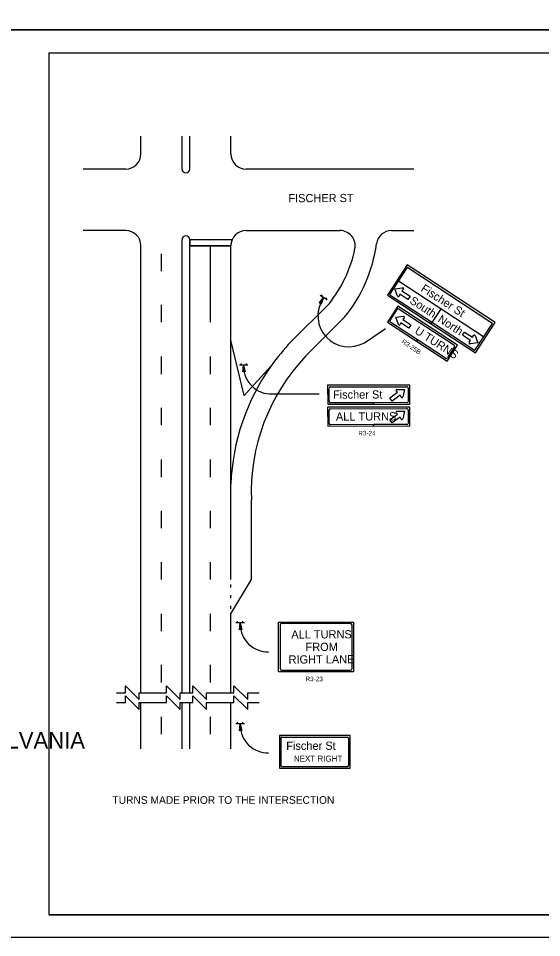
# Model space of a CAD drawing. Extents: x 644898 to 648326, y 298294 to 300670.
# Drawn here: x 646600 to 646943, y 298888 to 299490 of the extents above; entities that cross this region are included whole.
import ezdxf

# ---------------------------------------------------------------- set-up
doc = ezdxf.new("R2010")
doc.units = 0
for name, color, linetype in [('1', 7, 'Continuous'), ('2', 7, 'Continuous'), ('XCS-GRID-MIN', 7, 'Continuous')]:
    doc.layers.add(name, color=color, linetype=linetype)

msp = doc.modelspace()

# ---------------------------------------------------------------- linework, layer by layer
at = {"layer": '1'}
for p, q in [((646620.32, 299467.49), (647406.32, 299467.49)), ((646620.32, 299467.49), (646620.32, 298903.49)), ((647406.32, 298903.49), (646620.32, 298903.49)), ((646620.32, 298903.49), (647206.32, 298903.49))]:
    msp.add_line(p, q, dxfattribs=at)
at = {"layer": '2'}
for p, q in [((646680.58, 299401.42), (646680.58, 299412.84)), ((646707.46, 299391.42), (646707.46, 299412.84)), ((646712.55, 299391.42), (646712.55, 299412.84)), ((646739.42, 299401.42), (646739.42, 299412.84)), ((646670.58, 299391.42), (646642.84, 299391.42)), ((646859.13, 299391.42), (646749.42, 299391.42)), ((646670.58, 299351.17), (646642.84, 299351.17)), ((646749.42, 299351.17), (646810.8, 299351.17)), ((646844.69, 299351.17), (646859.13, 299351.17)), ((646707.46, 299167.76), (646707.46, 299345.17)), ((646712.55, 299167.76), (646712.55, 299345.17)), ((646740.26, 299345.17), (646712.55, 299345.17)), ((646680.58, 299167.76), (646680.58, 299341.17)), ((646739.42, 299341.17), (646712.55, 299341.17)), ((646726.05, 299291.14), (646726.05, 299341.17)), ((646739.42, 299279.33), (646739.42, 299341.17)), ((646694.08, 299324.64), (646694.08, 299336.01)), ((646854.81, 299328.7), (646841.95, 299308.85)), ((646843.42, 299309.37), (646854.83, 299326.84)), ((646912.36, 299291.05), (646854.81, 299328.7)), ((646855.27, 299326.95), (646910.33, 299290.84)), ((646846.71, 299313.09), (646851.77, 299313.7)), ((646848.51, 299308.22), (646846.71, 299313.09)), ((646849.2, 299318.29), (646904.82, 299281.86)), ((646852.36, 299312.69), (646851.41, 299311.67)), ((646802.47, 299305.72), (646797.87, 299308.72)), ((646798.7, 299308.17), (646799.32, 299309.12)), ((646801.63, 299306.26), (646802.25, 299307.21)), ((646841.95, 299308.85), (646869.52, 299290.81)), ((646870.05, 299291.62), (646843.53, 299308.94)), ((646850.1, 299309.45), (646849.58, 299308.24)), ((646855.34, 299306.02), (646850.1, 299309.45)), ((646851.41, 299311.67), (646856.74, 299308.14)), ((646856.74, 299308.14), (646855.34, 299306.02)), ((646694.08, 299291.14), (646694.08, 299302.51)), ((646778.77, 299278.34), (646803.69, 299303.26)), ((646848.72, 299301.64), (646841.98, 299291.24)), ((646887.77, 299276.09), (646848.72, 299301.64)), ((646843.78, 299292.32), (646848.34, 299299.41)), ((646847.33, 299294.46), (646852.39, 299295.07)), ((646849.14, 299289.58), (646847.33, 299294.46)), ((646849.72, 299299.76), (646885.27, 299276.57)), ((646877.01, 299300.07), (646870.63, 299290.32)), ((646788.51, 299269.08), (646813.67, 299294.24)), ((646841.98, 299291.24), (646861.05, 299278.82)), ((646861.52, 299279.59), (646844.07, 299291.03)), ((646850.72, 299290.82), (646850.2, 299289.61)), ((646855.96, 299287.39), (646850.72, 299290.82)), ((646852.98, 299294.06), (646852.03, 299293.04)), ((646852.03, 299293.04), (646857.36, 299289.51)), ((646857.36, 299289.51), (646855.96, 299287.39)), ((646870.05, 299291.62), (646869.52, 299290.81)), ((646869.52, 299290.81), (646870.05, 299291.62)), ((646869.52, 299290.81), (646899.49, 299271.2)), ((646898.69, 299272.92), (646870.05, 299291.62)), ((646910.45, 299290.41), (646899.12, 299273.04)), ((646899.49, 299271.2), (646912.36, 299291.05)), ((646826.85, 299277.78), (646840.71, 299287.04)), ((646891.09, 299282.63), (646892.49, 299284.76)), ((646896.42, 299279.11), (646891.09, 299282.63)), ((646892.49, 299284.76), (646897.73, 299281.32)), ((646897.73, 299281.32), (646898.25, 299282.53)), ((646899.31, 299282.56), (646901.12, 299277.69)), ((646739.42, 299167.76), (646739.42, 299279.33)), ((646861.05, 299278.82), (646861.52, 299279.59)), ((646861.52, 299279.59), (646861.05, 299278.82)), ((646861.05, 299278.82), (646880.99, 299265.72)), ((646879.86, 299267.67), (646861.52, 299279.59)), ((646895.47, 299278.08), (646896.42, 299279.11)), ((646901.12, 299277.69), (646896.06, 299277.07)), ((646880.99, 299265.72), (646887.77, 299276.09)), ((646885.76, 299275.02), (646881.17, 299268.01)), ((646694.08, 299257.26), (646694.08, 299268.64)), ((646726.05, 299257.26), (646726.05, 299268.64)), ((646750.57, 299263.11), (646745.07, 299263.11)), ((646746.07, 299263.11), (646746.07, 299264.23)), ((646749.57, 299263.11), (646749.57, 299264.23)), ((646856.7, 299249.96), (646802.8, 299249.96)), ((646802.8, 299249.96), (646802.85, 299237.57)), ((646803.76, 299239.45), (646803.73, 299247.91)), ((646804.67, 299248.92), (646854.34, 299249)), ((646848.59, 299245.34), (646847.64, 299246.25)), ((646847.98, 299247.26), (646853.18, 299247.25)), ((646853.18, 299247.25), (646851.99, 299242.3)), ((646855.6, 299247.97), (646855.6, 299239.59)), ((646856.7, 299237.57), (646856.7, 299249.96)), ((646766.45, 299244.23), (646797.31, 299244.23)), ((646843.55, 299241.63), (646848.59, 299245.34)), ((646845.05, 299239.57), (646843.55, 299241.63)), ((646850.21, 299243.34), (646845.05, 299239.57)), ((646850.84, 299242.1), (646850.21, 299243.34)), ((646694.08, 299223.76), (646694.08, 299235.14)), ((646726.05, 299223.76), (646726.05, 299235.14)), ((646856.7, 299235.62), (646802.8, 299235.62)), ((646802.8, 299235.62), (646802.85, 299223.23)), ((646802.85, 299237.57), (646832.84, 299237.62)), ((646804.67, 299234.59), (646854.34, 299234.66)), ((646832.81, 299238.51), (646804.75, 299238.42)), ((646854.69, 299238.58), (646832.81, 299238.51)), ((646832.84, 299237.62), (646832.81, 299238.51)), ((646832.81, 299238.51), (646832.84, 299237.62)), ((646832.84, 299237.62), (646856.7, 299237.57)), ((646856.7, 299223.23), (646856.7, 299235.62)), ((646803.76, 299225.12), (646803.73, 299233.58)), ((646843.55, 299227.29), (646848.59, 299231.01)), ((646850.21, 299229.01), (646845.05, 299225.24)), ((646848.59, 299231.01), (646847.64, 299231.92)), ((646847.98, 299232.92), (646853.18, 299232.92)), ((646850.84, 299227.76), (646850.21, 299229.01)), ((646853.18, 299232.92), (646851.99, 299227.96)), ((646855.6, 299233.63), (646855.6, 299225.25)), ((646802.85, 299223.23), (646832.84, 299223.28)), ((646832.81, 299224.18), (646804.75, 299224.09)), ((646854.69, 299224.25), (646832.81, 299224.18)), ((646832.84, 299223.28), (646832.81, 299224.18)), ((646832.81, 299224.18), (646832.84, 299223.28)), ((646832.84, 299223.28), (646856.7, 299223.23)), ((646845.05, 299225.24), (646843.55, 299227.29)), ((646694.08, 299189.89), (646694.08, 299201.26)), ((646726.05, 299189.89), (646726.05, 299201.26)), ((646752.88, 299167.76), (646752.88, 299174.67)), ((646680.58, 299048.76), (646680.58, 299167.76)), ((646694.08, 299156.39), (646694.08, 299167.76)), ((646707.46, 299048.76), (646707.46, 299167.76)), ((646712.55, 299048.76), (646712.55, 299167.76)), ((646726.05, 299156.39), (646726.05, 299167.76)), ((646739.42, 299122.89), (646739.42, 299167.76)), ((646752.88, 299122.89), (646752.88, 299167.76)), ((646694.08, 299122.89), (646694.08, 299134.26)), ((646726.05, 299122.89), (646726.05, 299134.26)), ((646739.42, 299100.39), (646752.88, 299122.89)), ((646739.42, 299117.64), (646739.42, 299119.64)), ((646739.42, 299110.64), (646739.42, 299112.64)), ((646739.42, 299103.64), (646739.42, 299105.64)), ((646694.08, 299089.01), (646694.08, 299100.39)), ((646726.05, 299089.01), (646726.05, 299100.39)), ((646739.42, 299048.76), (646739.42, 299100.39)), ((646748.29, 299094.42), (646742.79, 299094.42)), ((646743.79, 299094.42), (646743.79, 299095.55)), ((646747.29, 299094.42), (646747.29, 299095.55)), ((646770.64, 299062.5), (646770.64, 299095)), ((646770.64, 299095), (646794.31, 299095)), ((646771.64, 299093), (646771.64, 299064.5)), ((646794.31, 299094), (646772.64, 299094)), ((646794.31, 299094), (646794.31, 299095)), ((646794.31, 299095), (646819.77, 299095)), ((646794.31, 299095), (646794.31, 299094)), ((646817.77, 299094), (646794.31, 299094)), ((646818.77, 299064.5), (646818.77, 299093)), ((646819.77, 299095), (646819.77, 299062.5)), ((646694.08, 299055.51), (646694.08, 299066.89)), ((646726.05, 299055.51), (646726.05, 299066.89)), ((646819.77, 299062.5), (646770.64, 299062.5)), ((646772.64, 299063.5), (646817.77, 299063.5)), ((646664.5, 299048.76), (646670.38, 299048.76)), ((646679.38, 299048.76), (646697.25, 299048.76)), ((646706.25, 299048.76), (646713.75, 299048.76)), ((646708.71, 299048.76), (646714.58, 299048.76)), ((646723.58, 299048.76), (646741.46, 299048.76)), ((646750.46, 299048.76), (646757.96, 299048.76)), ((646664.5, 299042.26), (646670.38, 299042.26)), ((646679.38, 299042.26), (646697.25, 299042.26)), ((646680.58, 299012.09), (646680.58, 299042.26)), ((646706.25, 299042.26), (646713.75, 299042.26)), ((646707.46, 299012.09), (646707.46, 299042.26)), ((646708.71, 299042.26), (646714.58, 299042.26)), ((646712.55, 299012.09), (646712.55, 299042.26)), ((646723.58, 299042.26), (646741.46, 299042.26)), ((646739.42, 299012.09), (646739.42, 299042.26)), ((646750.46, 299042.26), (646757.96, 299042.26)), ((646694.08, 299021.64), (646694.08, 299033.01)), ((646726.05, 299021.64), (646726.05, 299033.01)), ((646748.29, 299028.35), (646742.79, 299028.35)), ((646743.79, 299028.35), (646743.79, 299029.48)), ((646747.29, 299028.35), (646747.29, 299029.48)), ((646817.43, 299020.67), (646771.36, 299020.67)), ((646771.36, 299020.67), (646771.36, 299012.25)), ((646772.36, 299012.25), (646772.36, 299019.42)), ((646772.61, 299019.67), (646815.62, 299019.67)), ((646816.52, 299018.78), (646816.49, 299001.34)), ((646817.43, 298999.3), (646817.43, 299020.67)), ((646772.36, 299012.25), (646771.36, 299012.25)), ((646771.36, 299012.25), (646771.36, 298999.3)), ((646771.36, 299012.25), (646772.36, 299012.25)), ((646772.36, 299000.55), (646772.36, 299012.25)), ((646815.56, 299000.3), (646772.61, 299000.3)), ((646771.36, 298999.3), (646817.43, 298999.3))]:
    msp.add_line(p, q, dxfattribs=at)
for points in [[(646740.26, 299345.17), (646712.55, 299345.17), (646712.55, 299341.17), (646726.05, 299341.17), (646739.42, 299341.17)], [(646797.64, 299303.8), (646797.92, 299303.76), (646800.06, 299307.29), (646797.64, 299303.8), (646797.29, 299303.72), (646800.06, 299307.29), (646798.33, 299303.49), (646798.48, 299303.25), (646800.06, 299307.29), (646798.62, 299303.01), (646798.48, 299303.25)], [(646765.9, 299262.74), (646748.22, 299243.14), (646739.42, 299279.33)], [(646747.57, 299258.86), (646747.82, 299258.98), (646747.7, 299263.11), (646747.57, 299258.86), (646747.32, 299258.61), (646747.7, 299263.11), (646748.32, 299258.98), (646748.57, 299258.86), (646747.7, 299263.11), (646748.82, 299258.73), (646748.57, 299258.86)], [(646745.29, 299090.17), (646745.54, 299090.3), (646745.42, 299094.42), (646745.29, 299090.17), (646745.04, 299089.92), (646745.42, 299094.42), (646746.04, 299090.3), (646746.29, 299090.17), (646745.42, 299094.42), (646746.54, 299090.05), (646746.29, 299090.17)], [(646670.38, 299048.76), (646670.38, 299053.26), (646679.38, 299044.26), (646679.38, 299048.76)], [(646697.25, 299048.76), (646697.25, 299053.26), (646706.25, 299044.26), (646706.25, 299048.76)], [(646714.58, 299048.76), (646714.58, 299053.26), (646723.58, 299044.26), (646723.58, 299048.76)], [(646741.46, 299048.76), (646741.46, 299053.26), (646750.46, 299044.26), (646750.46, 299048.76)], [(646670.38, 299042.26), (646670.38, 299046.76), (646679.38, 299037.76), (646679.38, 299042.26)], [(646697.25, 299042.26), (646697.25, 299046.76), (646706.25, 299037.76), (646706.25, 299042.26)], [(646714.58, 299042.26), (646714.58, 299046.76), (646723.58, 299037.76), (646723.58, 299042.26)], [(646741.46, 299042.26), (646741.46, 299046.76), (646750.46, 299037.76), (646750.46, 299042.26)], [(646745.29, 299024.1), (646745.54, 299024.23), (646745.42, 299028.35), (646745.29, 299024.1), (646745.04, 299023.85), (646745.42, 299028.35), (646746.04, 299024.23), (646746.29, 299024.1), (646745.42, 299028.35), (646746.54, 299023.98), (646746.29, 299024.1)]]:
    msp.add_lwpolyline(points, dxfattribs=at)
for centre, radius, start, end in [((646670.58, 299401.42), 10, 270, 0), ((646749.42, 299401.42), 10, 180, 270), ((646710, 299391.42), 2.55, 180, 360), ((646670.58, 299341.17), 10, 0, 90), ((646749.42, 299341.17), 10, 90, 180), ((646810.8, 299341.17), 10, 348.55632, 89.99983), ((646844.69, 299341.17), 10, 90.00056, 172.16517), ((646710, 299345.17), 2.55, 0, 180), ((646749.42, 299341.17), 10, 156.42182, 180), ((646738.85, 299355.73), 96.84, 320.58425, 352.16517), ((646738.85, 299355.73), 83.41, 321.01719, 348.55632), ((646855.15, 299326.7), 0.309, 57.18084, 146.82824), ((646851.89, 299313.09), 0.596, 317.2229, 101.12954), ((646843.83, 299309.24), 0.309, 147.40482, 234.67581), ((646849.05, 299308.55), 0.596, 199.55121, 337.07524), ((646816.72, 299295.4), 20.32, 147.29206, 299.90335), ((646852.51, 299294.46), 0.596, 317.2229, 101.12954), ((646849.67, 299289.91), 0.596, 199.55121, 337.07524), ((646910.27, 299290.63), 0.309, 325.62285, 56.69341), ((646898.78, 299282.23), 0.596, 19.55121, 157.07524), ((646882.46, 299179.66), 143.14, 136.41553, 144.51975), ((646895.94, 299277.68), 0.596, 137.2229, 281.12954), ((646898.97, 299273.2), 0.309, 236.60057, 328.41019), ((646882.46, 299179.66), 129.7, 136.41553, 182.21163), ((646880.33, 299268.51), 1, 237.56538, 328.05082), ((646882.46, 299179.66), 143.14, 144.51975, 177.78837), ((646765.83, 299262.23), 18.01, 180.38521, 271.96908), ((646848.11, 299246.64), 0.596, 89.18506, 226.70909), ((646851.38, 299242.4), 0.596, 206.85675, 350.76338), ((646804.71, 299239.47), 1, 181.51424, 269.92714), ((646854.62, 299239.54), 1, 270.76122, 1.24666), ((646848.11, 299232.31), 0.596, 89.18506, 226.70909), ((646804.71, 299225.13), 1, 181.51424, 269.92714), ((646851.38, 299228.06), 0.596, 206.85675, 350.76338), ((646854.62, 299225.2), 1, 270.76122, 1.24666), ((646763.55, 299093.54), 18.01, 180.38521, 271.96908), ((646772.64, 299093), 1, 90, 180), ((646817.77, 299093), 1, 0, 90), ((646772.64, 299064.5), 1, 180, 270), ((646817.77, 299064.5), 1, 270, 360), ((646763.55, 299027.47), 18.01, 180.38521, 271.96908), ((646772.61, 299019.42), 0.25, 90, 180)]:
    msp.add_arc(centre, radius, start, end, dxfattribs=at)
for centre, major_axis, ratio, start_param, end_param in [((646849.15, 299298.88), (0.566, 0.908), 0.876665, 6.253019, 7.809186), ((646844.66, 299291.86), (-1.1, 0), 0.830329, 5.730237, 7.273333), ((646884.7, 299275.71), (1.07, -0.7), 0.785349, 6.244238, 7.846016), ((646804.67, 299247.92), (0, 1.03), 0.878961, 6.274622, 7.830789), ((646854.34, 299247.96), (1.27, 0), 0.785349, 6.244238, 7.846016), ((646804.67, 299233.58), (0, 1.03), 0.878961, 6.274622, 7.830789), ((646854.34, 299233.62), (1.27, 0), 0.785349, 6.244238, 7.846016), ((646815.62, 299018.78), (-0.902, 0), 0.982846, 3.141593, 4.712389), ((646815.56, 299001.34), (0, -1.05), 0.891684, 0, 1.570796)]:
    msp.add_ellipse(centre, major_axis=major_axis, ratio=ratio, start_param=start_param, end_param=end_param, dxfattribs=at)
at = {"layer": 'XCS-GRID-MIN'}
for points in [[(646580.32, 300076.49), (647421.32, 300076.49), (647421.32, 299482.49), (646580.32, 299482.49)], [(646580.32, 299482.49), (647421.32, 299482.49), (647421.32, 298888.49), (646580.32, 298888.49)]]:
    msp.add_lwpolyline(points, close=True, dxfattribs=at)

# ---------------------------------------------------------------- texts
at = {"layer": '1'}
msp.add_text('COMMONWEALTH OF PENNSYLVANIA', height=10.7828, dxfattribs=at).set_placement((646377.92, 299012.23))
at = {"layer": '2'}
for s, height, rotation, p in [('FISCHER ST', 5.375, 0.20237, (646777.09, 299369.66)), ('Fischer St', 5.375, 326.8859, (646863.39, 299311.94)), ('South', 5.375, 326.8859, (646855.98, 299303.99)), ('North', 5.375, 326.8859, (646874.49, 299291.89)), ('U TURNS', 5.375, 327.00652, (646859.31, 299284.25)), ('R3-25B', 3, 326.19645, (646850.9, 299277.79)), ('Fischer St', 5.375, 0.20237, (646806.28, 299241.12)), ('ALL TURNS', 5.375, 0.20237, (646808.22, 299226.79)), ('ALL TURNS', 5.375, 0.20237, (646779.03, 299084.19)), ('FROM', 5.375, 0.20237, (646788.33, 299076.04)), ('RIGHT LANE', 5.375, 0.20237, (646777.22, 299067.81))]:
    msp.add_text(s, height=height, rotation=rotation, dxfattribs=at).set_placement(p)
for s, height, p in [('R3-24', 3, (646822.9, 299217.1)), ('R3-23', 3, (646788.35, 299056.27)), ('Fischer St', 5.375, (646775.7, 299011.36)), ('NEXT RIGHT', 3.917, (646780.68, 299003.66)), ('TURNS MADE PRIOR TO THE INTERSECTION', 5, (646661.93, 298976.05))]:
    msp.add_text(s, height=height, dxfattribs=at).set_placement(p)

doc.saveas('drawing.dxf')
